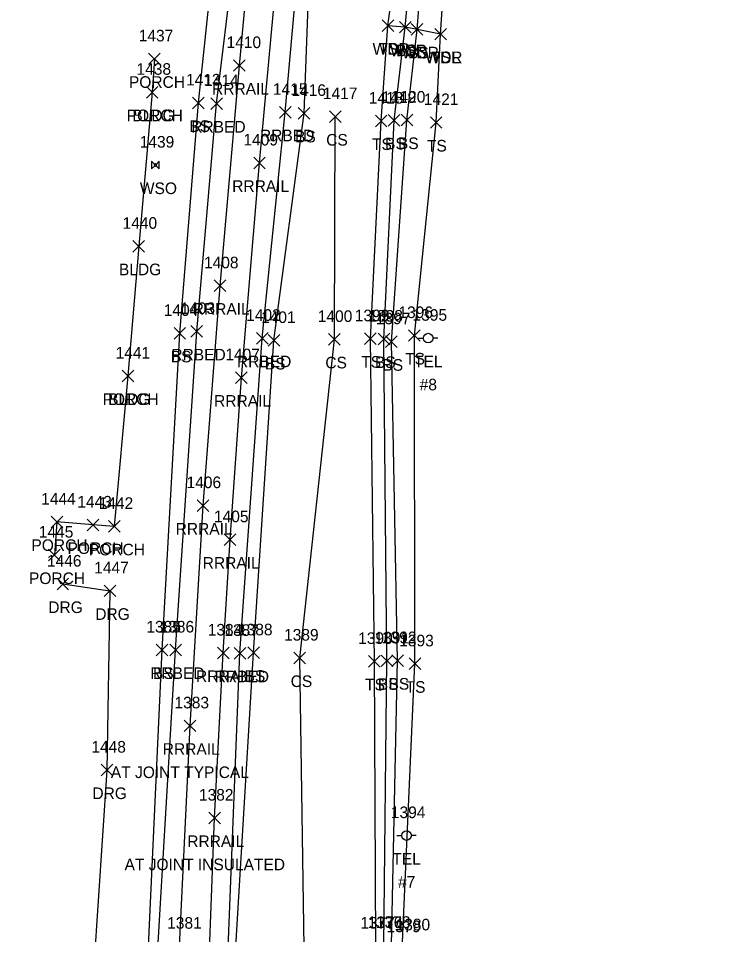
# Model space of a CAD drawing. Extents: x 1769141 to 1770817, y 735471 to 742405.
# Drawn here: x 1770127.9 to 1770251.8, y 741496 to 741653.9 of the extents above; entities that cross this region are included whole.
import ezdxf

# ---------------------------------------------------------------- set-up
doc = ezdxf.new("R2010")
doc.units = 0
for name, color, linetype in [('L_A', 7, 'Continuous'), ('L_I', 7, 'Continuous'), ('L_TIC', 7, 'Continuous'), ('LAWA', 7, 'Continuous'), ('LBC', 7, 'Continuous'), ('LBF', 7, 'Continuous'), ('LELB', 7, 'Continuous'), ('R_A', 7, 'Continuous'), ('R_C', 7, 'Continuous'), ('R_I', 7, 'Continuous'), ('R_TIC', 7, 'Continuous'), ('RDG', 7, 'Continuous'), ('RR', 7, 'Continuous'), ('RRB', 7, 'Continuous'), ('U_A', 7, 'Continuous'), ('U_C', 7, 'Continuous'), ('U_I', 7, 'Continuous'), ('UP', 7, 'Continuous'), ('UWV', 7, 'Continuous')]:
    doc.layers.add(name, color=color, linetype=linetype)

msp = doc.modelspace()

# ---------------------------------------------------------------- linework, layer by layer
at = {"layer": 'L_TIC'}
for points in [[(1770190.59, 741651.63), (1770192.59, 741653.63)], [(1770192.59, 741651.63), (1770190.59, 741653.63)], [(1770190.59, 741651.63), (1770192.59, 741653.63)], [(1770192.59, 741651.63), (1770190.59, 741653.63)], [(1770193.58, 741651.38), (1770195.58, 741653.38)], [(1770195.58, 741651.38), (1770193.58, 741653.38)], [(1770193.58, 741651.38), (1770195.58, 741653.38)], [(1770195.58, 741651.38), (1770193.58, 741653.38)], [(1770195.63, 741651), (1770197.63, 741653)], [(1770197.63, 741651), (1770195.63, 741653)], [(1770195.63, 741651), (1770197.63, 741653)], [(1770197.63, 741651), (1770195.63, 741653)], [(1770199.67, 741650.18), (1770201.67, 741652.18)], [(1770201.67, 741650.18), (1770199.67, 741652.18)], [(1770199.67, 741650.18), (1770201.67, 741652.18)], [(1770201.67, 741650.18), (1770199.67, 741652.18)], [(1770199.67, 741650.18), (1770201.67, 741652.18)], [(1770201.67, 741650.18), (1770199.67, 741652.18)], [(1770150.37, 741645.93), (1770152.37, 741647.93)], [(1770152.37, 741645.93), (1770150.37, 741647.93)], [(1770149.99, 741640.18), (1770151.99, 741642.18)], [(1770151.99, 741640.18), (1770149.99, 741642.18)], [(1770149.99, 741640.18), (1770151.99, 741642.18)], [(1770151.99, 741640.18), (1770149.99, 741642.18)], [(1770157.96, 741638.34), (1770159.96, 741640.34)], [(1770159.96, 741638.34), (1770157.96, 741640.34)], [(1770176.16, 741636.54), (1770178.16, 741638.54)], [(1770178.16, 741636.54), (1770176.16, 741638.54)], [(1770181.53, 741635.98), (1770183.53, 741637.98)], [(1770183.53, 741635.98), (1770181.53, 741637.98)], [(1770189.44, 741635.22), (1770191.44, 741637.22)], [(1770191.44, 741635.22), (1770189.44, 741637.22)], [(1770191.66, 741635.32), (1770193.66, 741637.32)], [(1770193.66, 741635.32), (1770191.66, 741637.32)], [(1770193.88, 741635.38), (1770195.88, 741637.38)], [(1770195.88, 741635.38), (1770193.88, 741637.38)], [(1770198.91, 741634.96), (1770200.91, 741636.96)], [(1770200.91, 741634.96), (1770198.91, 741636.96)], [(1770147.68, 741613.65), (1770149.68, 741615.65)], [(1770149.68, 741613.65), (1770147.68, 741615.65)], [(1770154.76, 741598.64), (1770156.76, 741600.64)], [(1770156.76, 741598.64), (1770154.76, 741600.64)], [(1770170.96, 741597.42), (1770172.96, 741599.42)], [(1770172.96, 741597.42), (1770170.96, 741599.42)], [(1770181.37, 741597.6), (1770183.37, 741599.6)], [(1770183.37, 741597.6), (1770181.37, 741599.6)], [(1770187.59, 741597.72), (1770189.59, 741599.72)], [(1770189.59, 741597.72), (1770187.59, 741599.72)], [(1770189.92, 741597.66), (1770191.92, 741599.66)], [(1770191.92, 741597.66), (1770189.92, 741599.66)], [(1770191.21, 741597.2), (1770193.21, 741599.2)], [(1770193.21, 741597.2), (1770191.21, 741599.2)], [(1770195.16, 741598.27), (1770197.16, 741600.27)], [(1770197.16, 741598.27), (1770195.16, 741600.27)], [(1770145.82, 741591.3), (1770147.82, 741593.3)], [(1770147.82, 741591.3), (1770145.82, 741593.3)], [(1770145.82, 741591.3), (1770147.82, 741593.3)], [(1770147.82, 741591.3), (1770145.82, 741593.3)], [(1770133.58, 741566.15), (1770135.58, 741568.15)], [(1770135.58, 741566.15), (1770133.58, 741568.15)], [(1770139.79, 741565.63), (1770141.79, 741567.63)], [(1770141.79, 741565.63), (1770139.79, 741567.63)], [(1770143.47, 741565.39), (1770145.47, 741567.39)], [(1770145.47, 741565.39), (1770143.47, 741567.39)], [(1770133.16, 741560.45), (1770135.16, 741562.45)], [(1770135.16, 741560.45), (1770133.16, 741562.45)], [(1770151.69, 741544.1), (1770153.69, 741546.1)], [(1770153.69, 741544.1), (1770151.69, 741546.1)], [(1770167.47, 741543.61), (1770169.47, 741545.61)], [(1770169.47, 741543.61), (1770167.47, 741545.61)], [(1770175.41, 741542.71), (1770177.41, 741544.71)], [(1770177.41, 741542.71), (1770175.41, 741544.71)], [(1770188.26, 741542.13), (1770190.26, 741544.13)], [(1770190.26, 741542.13), (1770188.26, 741544.13)], [(1770190.42, 741542.22), (1770192.42, 741544.22)], [(1770192.42, 741542.22), (1770190.42, 741544.22)], [(1770192.26, 741542.26), (1770194.26, 741544.26)], [(1770194.26, 741542.26), (1770192.26, 741544.26)], [(1770195.24, 741541.72), (1770197.24, 741543.72)], [(1770197.24, 741541.72), (1770195.24, 741543.72)]]:
    msp.add_lwpolyline(points, dxfattribs=at)
at = {"layer": 'LAWA'}
for points in [[(1770200.67, 741651.18), (1770196.63, 741652), (1770194.58, 741652.38), (1770191.59, 741652.63), (1770194.77, 741675.94), (1770196.6, 741721.64), (1770202.88, 741764.64), (1770208.31, 741805.67), (1770212.68, 741843.55)], [(1770200.67, 741651.18), (1770202.39, 741676.46), (1770206.62, 741720.21), (1770214.9, 741763.35), (1770219.05, 741807.6), (1770222.48, 741841.68), (1770219.97, 741843.04), (1770214.71, 741843.41), (1770212.68, 741843.55)]]:
    msp.add_lwpolyline(points, dxfattribs=at)
at = {"layer": 'LBC'}
msp.add_lwpolyline([(1770150.99, 741641.18), (1770148.68, 741614.65), (1770146.82, 741592.3)], dxfattribs=at)
at = {"layer": 'LBF'}
for points in [[(1770151.37, 741646.93), (1770150.99, 741641.18)], [(1770146.82, 741592.3), (1770144.47, 741566.39), (1770140.79, 741566.63), (1770134.58, 741567.15), (1770134.16, 741561.45)]]:
    msp.add_lwpolyline(points, dxfattribs=at)
at = {"layer": 'LELB'}
for points in [[(1770189.82, 741481.43), (1770190.88, 741494.18), (1770191.42, 741543.22), (1770190.92, 741598.66), (1770192.66, 741636.32), (1770194.58, 741652.38), (1770196.84, 741676.51), (1770200.25, 741721.67), (1770205.66, 741764.05), (1770211.04, 741807.24), (1770214.71, 741843.41), (1770218.13, 741875.72), (1770220.67, 741890.47)], [(1770189.51, 741370.79), (1770192.33, 741421.87), (1770190.52, 741443.62), (1770191.25, 741465.52), (1770192.9, 741467.86), (1770192.23, 741494.22), (1770193.26, 741543.26), (1770192.21, 741598.2), (1770194.88, 741636.38), (1770196.63, 741652), (1770198.6, 741676.72), (1770202.3, 741721.55), (1770209.33, 741763.66), (1770214.61, 741807.75), (1770219.97, 741843.04), (1770223.09, 741876.08), (1770226.05, 741889.39), (1770243.39, 741887.35), (1770251.84, 741882.91)], [(1770159.47, 741122.16), (1770155.88, 741129.72), (1770152.26, 741191.83), (1770148.79, 741250.94), (1770147.9, 741304.26), (1770146.46, 741364.5), (1770147.88, 741419.38), (1770149.7, 741479.08), (1770152.69, 741545.1), (1770155.76, 741599.64), (1770158.96, 741639.34), (1770162.27, 741670.36), (1770169.16, 741728.31), (1770174.08, 741769.97), (1770179.32, 741804.69), (1770187.63, 741847.88), (1770194.61, 741886.57)], [(1770170.72, 741118.89), (1770170.78, 741142.85), (1770168.08, 741192.95), (1770167.14, 741250.65), (1770163.56, 741305.09), (1770162.91, 741364.69), (1770162.95, 741418.42), (1770164.45, 741477.75), (1770168.47, 741544.61), (1770171.96, 741598.42), (1770177.16, 741637.54), (1770178.36, 741670.05), (1770184.18, 741725.16), (1770189.43, 741766.84), (1770194.19, 741801.42), (1770201.5, 741845.17), (1770207.42, 741883.86)], [(1770186.17, 741371.3), (1770187.18, 741421.88), (1770188.97, 741458.59), (1770189.13, 741469.78), (1770189.82, 741481.43), (1770189.54, 741494.09), (1770189.26, 741543.13), (1770188.59, 741598.72), (1770190.44, 741636.22), (1770191.59, 741652.63)], [(1770194.21, 741443.24), (1770192.49, 741443.85), (1770192.9, 741467.86), (1770194.03, 741493.48), (1770196.24, 741542.72), (1770196.16, 741599.27), (1770199.91, 741635.96), (1770200.67, 741651.18)], [(1770175.78, 741384.28), (1770175.87, 741421.05), (1770176.49, 741448.31), (1770177.38, 741478.5), (1770176.41, 741543.71), (1770182.37, 741598.6), (1770182.53, 741636.98)]]:
    msp.add_lwpolyline(points, dxfattribs=at)
at = {"layer": 'R_TIC'}
for points in [[(1770165.02, 741644.78), (1770167.02, 741646.78)], [(1770167.02, 741644.78), (1770165.02, 741646.78)], [(1770161.08, 741638.22), (1770163.08, 741640.22)], [(1770163.08, 741638.22), (1770161.08, 741640.22)], [(1770172.92, 741636.73), (1770174.92, 741638.73)], [(1770174.92, 741636.73), (1770172.92, 741638.73)], [(1770168.48, 741628), (1770170.48, 741630)], [(1770170.48, 741628), (1770168.48, 741630)], [(1770161.69, 741606.84), (1770163.69, 741608.84)], [(1770163.69, 741606.84), (1770161.69, 741608.84)], [(1770157.66, 741598.97), (1770159.66, 741600.97)], [(1770159.66, 741598.97), (1770157.66, 741600.97)], [(1770168.96, 741597.79), (1770170.96, 741599.79)], [(1770170.96, 741597.79), (1770168.96, 741599.79)], [(1770165.37, 741591), (1770167.37, 741593)], [(1770167.37, 741591), (1770165.37, 741593)], [(1770158.75, 741568.97), (1770160.75, 741570.97)], [(1770160.75, 741568.97), (1770158.75, 741570.97)], [(1770163.41, 741563.1), (1770165.41, 741565.1)], [(1770165.41, 741563.1), (1770163.41, 741565.1)], [(1770134.61, 741555.46), (1770136.61, 741557.46)], [(1770136.61, 741555.46), (1770134.61, 741557.46)], [(1770142.71, 741554.28), (1770144.71, 741556.28)], [(1770144.71, 741554.28), (1770142.71, 741556.28)], [(1770154.02, 741544.1), (1770156.02, 741546.1)], [(1770156.02, 741544.1), (1770154.02, 741546.1)], [(1770162.25, 741543.58), (1770164.25, 741545.58)], [(1770164.25, 741543.58), (1770162.25, 741545.58)], [(1770165.12, 741543.52), (1770167.12, 741545.52)], [(1770167.12, 741543.52), (1770165.12, 741545.52)], [(1770156.53, 741531.03), (1770158.53, 741533.03)], [(1770158.53, 741531.03), (1770156.53, 741533.03)], [(1770142.21, 741523.41), (1770144.21, 741525.41)], [(1770144.21, 741523.41), (1770142.21, 741525.41)], [(1770160.75, 741515.15), (1770162.75, 741517.15)], [(1770162.75, 741515.15), (1770160.75, 741517.15)]]:
    msp.add_lwpolyline(points, dxfattribs=at)
at = {"layer": 'RDG'}
msp.add_lwpolyline([(1770135.61, 741556.46), (1770143.71, 741555.28), (1770143.21, 741524.41), (1770140.94, 741490.62), (1770127.94, 741469.47)], dxfattribs=at)
at = {"layer": 'RR'}
for points in [[(1770158.42, 741192.16), (1770156.87, 741228.02), (1770155.37, 741265.98), (1770154.18, 741304.01), (1770153.58, 741341.98), (1770153.36, 741379.98), (1770153.72, 741418.09), (1770154.5, 741456.02), (1770155.71, 741494.07), (1770157.53, 741532.03), (1770159.75, 741569.97), (1770162.69, 741607.84), (1770166.02, 741645.78), (1770168.28, 741669.99)], [(1770164.28, 741173.16), (1770162.44, 741212.29), (1770160.95, 741250.16), (1770159.49, 741288.14), (1770158.69, 741326.21), (1770158.25, 741364.2), (1770158.38, 741402.17), (1770159.01, 741439.19), (1770160.27, 741478.16), (1770161.75, 741516.15), (1770163.25, 741544.58), (1770164.41, 741564.1), (1770166.37, 741592), (1770169.48, 741629), (1770173.06, 741667.73)]]:
    msp.add_lwpolyline(points, dxfattribs=at)
at = {"layer": 'RRB'}
for points in [[(1770159.47, 741122.16), (1770157.22, 741138.41), (1770154.83, 741192.11), (1770151.88, 741250.64), (1770151.59, 741304.35), (1770150.34, 741364.24), (1770150.63, 741419.36), (1770151.12, 741479.07), (1770155.02, 741545.1), (1770158.66, 741599.97), (1770162.08, 741639.22), (1770165.85, 741670.35), (1770171.87, 741726.99), (1770176.74, 741769), (1770181.57, 741804.32), (1770188.88, 741847.51), (1770194.61, 741886.57), (1770198.24, 741898.62)], [(1770170.72, 741118.89), (1770169.25, 741143.07), (1770166.39, 741192.95), (1770164.02, 741250.29), (1770162.37, 741304.75), (1770161.63, 741364.62), (1770161.73, 741418.13), (1770163.48, 741477.78), (1770166.12, 741544.52), (1770169.96, 741598.79), (1770173.92, 741637.73), (1770176.8, 741669.78), (1770182.94, 741725.6), (1770188.11, 741766.81), (1770193.15, 741801.76), (1770199.69, 741845.61), (1770207.42, 741883.86)]]:
    msp.add_lwpolyline(points, dxfattribs=at)
at = {"layer": 'UP'}
for p, q in [((1770196.87, 741598.81), (1770197.7, 741598.81)), ((1770198.53, 741598.81), (1770198.53, 741598.81)), ((1770200.2, 741598.81), (1770199.36, 741598.81)), ((1770199.36, 741598.81), (1770199.36, 741598.81)), ((1770200.2, 741598.81), (1770200.2, 741598.81)), ((1770193.14, 741513.13), (1770193.97, 741513.13)), ((1770194.8, 741513.13), (1770194.8, 741513.13)), ((1770196.47, 741513.13), (1770195.64, 741513.13)), ((1770195.64, 741513.13), (1770195.64, 741513.13)), ((1770196.47, 741513.13), (1770196.47, 741513.13))]:
    msp.add_line(p, q, dxfattribs=at)
for centre in [(1770198.53, 741598.81), (1770194.8, 741513.13)]:
    msp.add_circle(centre, 0.833, dxfattribs=at)
at = {"layer": 'UWV'}
for p, q in [((1770150.89, 741629.3), (1770151.44, 741628.75)), ((1770152.22, 741629.3), (1770151.67, 741628.75)), ((1770151.44, 741628.52), (1770150.89, 741627.97)), ((1770151.67, 741628.52), (1770152.22, 741627.97))]:
    msp.add_line(p, q, dxfattribs=at)
for points in [[(1770150.89, 741629.3), (1770150.89, 741627.97)], [(1770152.22, 741627.97), (1770152.22, 741629.3)]]:
    msp.add_lwpolyline(points, dxfattribs=at)
msp.add_lwpolyline([(1770151.79, 741628.63), (1770151.55, 741628.87), (1770151.32, 741628.63), (1770151.55, 741628.4)], close=True, dxfattribs=at)

# ---------------------------------------------------------------- texts
at = {"layer": 'L_A'}
for s, p in [('WDR', (1770188.96, 741647.63)), ('TS', (1770190, 741647.63)), ('WDR', (1770191.95, 741647.38)), ('BS', (1770193.02, 741647.38)), ('WDR', (1770193.99, 741647)), ('BS', (1770195.07, 741647)), ('WDR', (1770198.04, 741646.18)), ('WDL', (1770198.09, 741646.18)), ('TS', (1770199.08, 741646.18)), ('PORCH', (1770146.99, 741641.93)), ('PORCH', (1770146.61, 741636.18)), ('BLDG', (1770147.58, 741636.18)), ('BS', (1770157.4, 741634.34)), ('BS', (1770175.61, 741632.54)), ('CS', (1770180.97, 741631.98)), ('TS', (1770188.85, 741631.22)), ('BS', (1770191.11, 741631.32)), ('BS', (1770193.32, 741631.38)), ('TS', (1770198.32, 741630.96)), ('BLDG', (1770145.27, 741609.65)), ('BS', (1770154.2, 741594.64)), ('TS', (1770194.57, 741594.27)), ('BS', (1770170.4, 741593.42)), ('CS', (1770180.82, 741593.6)), ('TS', (1770187, 741593.72)), ('BS', (1770189.36, 741593.66)), ('BS', (1770190.65, 741593.2)), ('PORCH', (1770142.45, 741587.3)), ('BLDG', (1770143.41, 741587.3)), ('PORCH', (1770130.2, 741562.15)), ('PORCH', (1770136.42, 741561.63)), ('PORCH', (1770140.09, 741561.39)), ('PORCH', (1770129.78, 741556.45)), ('BS', (1770151.13, 741540.1)), ('BS', (1770166.91, 741539.61)), ('CS', (1770174.85, 741538.71)), ('TS', (1770187.67, 741538.13)), ('BS', (1770189.86, 741538.22)), ('BS', (1770191.7, 741538.26)), ('TS', (1770194.65, 741537.72))]:
    msp.add_text(s, height=2, dxfattribs=at).set_placement(p)
at = {"layer": 'L_I'}
for s, p in [('1437', (1770148.68, 741649.93)), ('1438', (1770148.3, 741644.18)), ('1438', (1770148.3, 741644.18)), ('1413', (1770156.83, 741642.34)), ('1416', (1770174.98, 741640.54)), ('1417', (1770180.4, 741639.98)), ('1418', (1770188.31, 741639.22)), ('1419', (1770190.53, 741639.32)), ('1420', (1770192.1, 741639.38)), ('1421', (1770197.79, 741638.96)), ('1440', (1770145.9, 741617.65)), ('1404', (1770152.99, 741602.64)), ('1396', (1770193.41, 741602.27)), ('1401', (1770169.75, 741601.42)), ('1400', (1770179.52, 741601.6)), ('1399', (1770185.89, 741601.72)), ('1398', (1770188.23, 741601.66)), ('1397', (1770189.52, 741601.2)), ('1441', (1770144.7, 741595.3)), ('1441', (1770144.7, 741595.3)), ('1444', (1770131.88, 741570.15)), ('1443', (1770138.1, 741569.63)), ('1442', (1770141.78, 741569.39)), ('1445', (1770131.47, 741564.45)), ('1385', (1770149.99, 741548.1)), ('1388', (1770165.78, 741547.61)), ('1389', (1770173.71, 741546.71)), ('1390', (1770186.48, 741546.13)), ('1391', (1770189.29, 741546.22)), ('1392', (1770190.57, 741546.26)), ('1393', (1770193.55, 741545.72)), ('1377', (1770186.85, 741497.09)), ('1376', (1770188.13, 741497.18)), ('1378', (1770189.54, 741497.22)), ('1379', (1770191.33, 741496.48)), ('1380', (1770192.92, 741496.79))]:
    msp.add_text(s, height=2, dxfattribs=at).set_placement(p)
at = {"layer": 'R_A'}
for s, p in [('RRRAIL', (1770161.31, 741640.78)), ('RRBED', (1770157.73, 741634.22)), ('RRBED', (1770169.56, 741632.73)), ('RRRAIL', (1770164.78, 741624)), ('RRRAIL', (1770157.98, 741602.84)), ('RRBED', (1770154.3, 741594.97)), ('RRBED', (1770165.6, 741593.79)), ('RRRAIL', (1770161.66, 741587)), ('RRRAIL', (1770155.04, 741564.97)), ('RRRAIL', (1770159.7, 741559.1)), ('DRG', (1770133.1, 741551.46)), ('DRG', (1770141.19, 741550.28)), ('RRBED', (1770150.66, 741540.1)), ('RRRAIL', (1770158.54, 741539.58)), ('RRBED', (1770161.76, 741539.52)), ('RRRAIL', (1770152.82, 741527.03)), ('DRG', (1770140.7, 741519.41)), ('RRRAIL', (1770157.04, 741511.15))]:
    msp.add_text(s, height=2, dxfattribs=at).set_placement(p)
at = {"layer": 'R_C'}
for s, p in [('AT JOINT TYPICAL', (1770143.88, 741523.03)), ('AT JOINT INSULATED', (1770146.24, 741507.15))]:
    msp.add_text(s, height=2, dxfattribs=at).set_placement(p)
at = {"layer": 'R_I'}
for s, p in [('1410', (1770163.81, 741648.78)), ('1414', (1770159.95, 741642.22)), ('1415', (1770171.79, 741640.73)), ('1409', (1770166.71, 741632)), ('1408', (1770159.92, 741610.84)), ('1403', (1770155.88, 741602.97)), ('1402', (1770167.19, 741601.79)), ('1407', (1770163.6, 741595)), ('1406', (1770156.92, 741572.97)), ('1405', (1770161.64, 741567.1)), ('1446', (1770132.87, 741559.46)), ('1447', (1770141.01, 741558.28)), ('1386', (1770152.27, 741548.1)), ('1384', (1770160.56, 741547.58)), ('1387', (1770163.43, 741547.52)), ('1383', (1770154.84, 741535.03)), ('1448', (1770140.52, 741527.41)), ('1382', (1770159.05, 741519.15)), ('1381', (1770153.58, 741497.07))]:
    msp.add_text(s, height=2, dxfattribs=at).set_placement(p)
at = {"layer": 'U_A'}
for s, p in [('WSO', (1770148.88, 741623.63)), ('TEL', (1770196.09, 741593.81)), ('TEL', (1770192.36, 741508.13))]:
    msp.add_text(s, height=2, dxfattribs=at).set_placement(p)
at = {"layer": 'U_C'}
for s, p in [('#8', (1770197.07, 741589.81)), ('#7', (1770193.34, 741504.13))]:
    msp.add_text(s, height=2, dxfattribs=at).set_placement(p)
at = {"layer": 'U_I'}
for s, p in [('1439', (1770148.85, 741631.63)), ('1395', (1770195.84, 741601.81)), ('1394', (1770192.11, 741516.13))]:
    msp.add_text(s, height=2, dxfattribs=at).set_placement(p)

doc.saveas('drawing.dxf')
